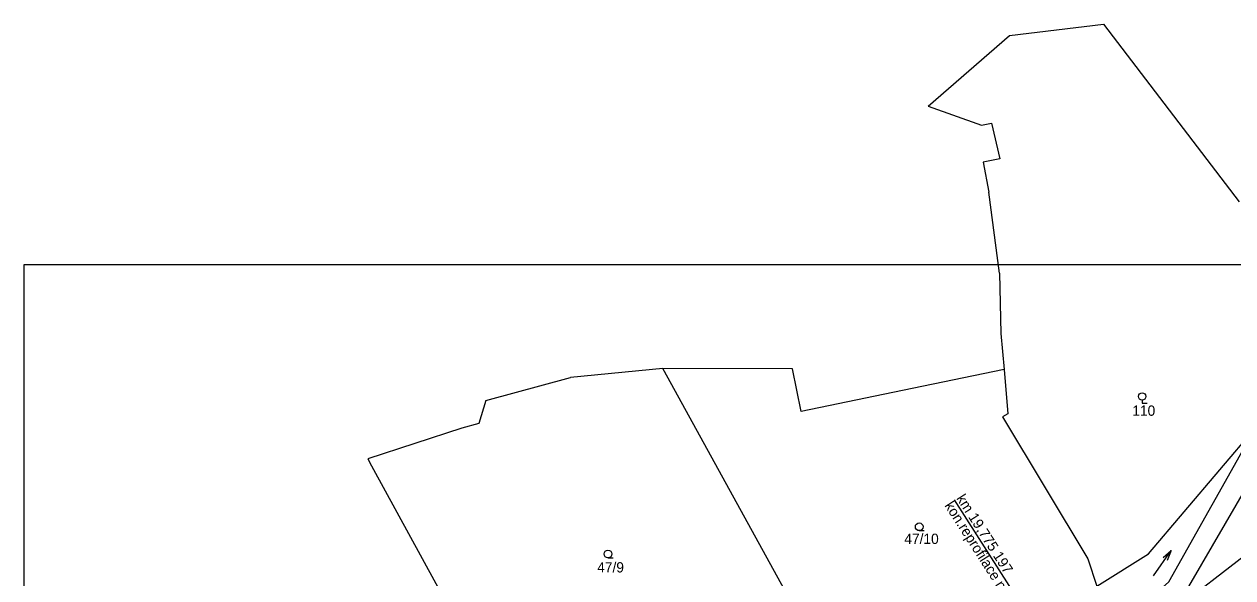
# Model space of a CAD drawing. Extents: x -752184 to -751416, y -1028299 to -1027836.
# Drawn here: x -751880.8 to -751645.5, y -1027958.6 to -1027850.8 of the extents above; entities that cross this region are included whole.
import ezdxf

# ---------------------------------------------------------------- set-up
doc = ezdxf.new("R2010")
doc.units = 0
for name, color, linetype in [('SO 201 Popisy', 7, 'Continuous'), ('Vrstva 4', 7, 'Continuous'), ('Vrstva 55', 7, 'Continuous'), ('Vrstva 57', 7, 'Continuous'), ('Vrstva 58', 7, 'Continuous')]:
    doc.layers.add(name, color=color, linetype=linetype)

msp = doc.modelspace()

# ---------------------------------------------------------------- linework, layer by layer
at = {"layer": 'SO 201 Popisy'}
msp.add_line((-751699.8, -1027943.39), (-751673.49, -1027984.52), dxfattribs=at)
at = {"layer": 'Vrstva 4'}
msp.add_lwpolyline([(-751880.79, -1027897.6), (-751466.79, -1027897.6), (-751466.79, -1028188.6), (-751880.79, -1028188.6)], close=True, dxfattribs=at)
at = {"layer": 'Vrstva 55'}
for p, q in [((-751670.74, -1027850.8), (-751644.31, -1027885.35)), ((-751704.87, -1027866.74), (-751694.47, -1027870.45)), ((-751690.99, -1027899.26), (-751693.06, -1027883.49)), ((-751656.71, -1027964.65), (-751615.69, -1027894.18)), ((-751690.99, -1027899.26), (-751690.67, -1027911.02)), ((-751690.67, -1027911.02), (-751690.06, -1027918.02)), ((-751756.49, -1027917.81), (-751774.43, -1027919.56)), ((-751721.34, -1027981.66), (-751756.49, -1027917.81)), ((-751731.23, -1027917.9), (-751756.49, -1027917.81)), ((-751729.53, -1027926.17), (-751731.23, -1027917.9)), ((-751690.06, -1027918.02), (-751709.85, -1027922.12)), ((-751790.91, -1027924.02), (-751774.43, -1027919.56)), ((-751790.91, -1027924.02), (-751792.3, -1027928.54)), ((-751709.85, -1027922.12), (-751729.53, -1027926.17)), ((-751792.3, -1027928.54), (-751795.59, -1027929.43)), ((-751795.59, -1027929.43), (-751813.91, -1027935.42)), ((-751813.91, -1027935.42), (-751813.18, -1027936.76)), ((-751813.18, -1027936.76), (-751798.39, -1027963.79))]:
    msp.add_line(p, q, dxfattribs=at)
for points in [[(-751704.87, -1027866.74), (-751689.01, -1027853.02), (-751670.74, -1027850.8)], [(-751694.47, -1027870.45), (-751692.52, -1027870.09), (-751690.89, -1027877.03), (-751694.15, -1027877.64), (-751693.06, -1027883.49)], [(-751690.06, -1027918.02), (-751689.33, -1027926.62), (-751690.4, -1027927.23), (-751673.79, -1027954.88), (-751672, -1027960.17)], [(-751672, -1027960.17), (-751661.99, -1027953.87), (-751641.14, -1027929.37)], [(-751668.79, -1027968.97), (-751658.03, -1027959.34), (-751641.14, -1027929.37)], [(-751626.99, -1027930.26), (-751643.3, -1027954.3), (-751656.71, -1027964.65)]]:
    msp.add_lwpolyline(points, dxfattribs=at)
at = {"layer": 'Vrstva 58'}
for p, q in [((-751663.2, -1027923.99), (-751663.2, -1027924.54)), ((-751663.2, -1027924.54), (-751662.2, -1027924.54)), ((-751706.59, -1027949.38), (-751705.59, -1027949.38)), ((-751661.01, -1027958.18), (-751657.56, -1027953.27)), ((-751767.16, -1027954.67), (-751766.16, -1027954.67))]:
    msp.add_line(p, q, dxfattribs=at)
msp.add_lwpolyline([(-751659.12, -1027954.62), (-751657.56, -1027953.27), (-751658.3, -1027955.2)], dxfattribs=at)
for centre, radius in [((-751663.2, -1027923.26), 0.725), ((-751706.59, -1027948.63), 0.75), ((-751767.16, -1027953.92), 0.75)]:
    msp.add_circle(centre, radius, dxfattribs=at)

# ---------------------------------------------------------------- texts
at = {"layer": 'SO 201 Popisy'}
for s, p in [('km 19,775 197', (-751699.43, -1027943.09)), ('kon.reprofilace nást.hrany k.č.3', (-751701.73, -1027944.49))]:
    msp.add_text(s, height=2, rotation=302.5983, dxfattribs=at).set_placement(p)
at = {"layer": 'Vrstva 57'}
for s, p in [('110', (-751665.11, -1027927.02)), ('47/10', (-751709.48, -1027951.97)), ('47/9', (-751769.26, -1027957.52))]:
    msp.add_text(s, height=2, dxfattribs=at).set_placement(p)

doc.saveas('drawing.dxf')
